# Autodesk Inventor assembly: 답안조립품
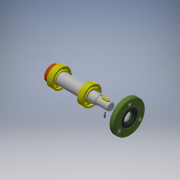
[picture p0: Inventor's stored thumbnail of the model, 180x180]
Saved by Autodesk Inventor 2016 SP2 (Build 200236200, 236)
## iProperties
Created: 2017-09
Part Number: 답안조립품
Document SubType Name: Assembly
Designer: Administrator
Author: Administrator
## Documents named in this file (11)
- D:\470907V1010\답안조립품.iam
- D:\470907V1010\본체.ipt
- D:\470907V1010\커버.ipt
- D:\470907V1010\볼트 M4 x 12.ipt
- D:\470907V1010\축.ipt
- D:\470907V1010\키 5 x 5 x 16.ipt
- D:\470907V1010\베어링 6004.ipt
- D:\470907V1010\오일 실 20x35x7.ipt
- D:\470907V1010\V벨트풀리.ipt
- D:\470907V1010\멈춤나사 M3x8.ipt
- D:\470907V1010\어댑터슬리브.ipt
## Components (1 placed, 1 different names)
1. V벨트풀리:1
